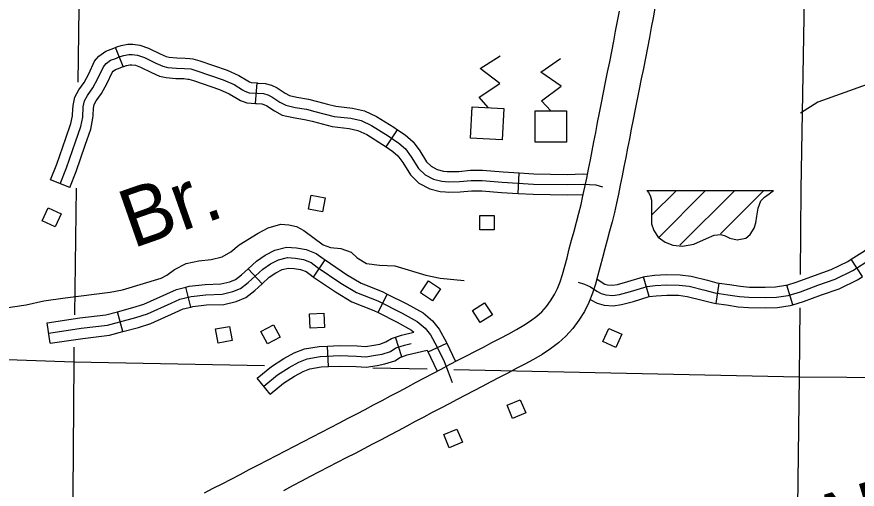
# Model space of a CAD drawing. Extents: x 1370130 to 1380143, y 377636 to 380256.
# Drawn here: x 1377386.4 to 1377557.8, y 379444.4 to 379540.8 of the extents above; entities that cross this region are included whole.
import ezdxf

# ---------------------------------------------------------------- set-up
doc = ezdxf.new("R2010")
doc.units = 0
for name, color, linetype in [('Level 10', 7, 'Continuous'), ('Level 32', 7, 'Continuous'), ('Level 35', 7, 'Continuous'), ('Level 40', 7, 'Continuous'), ('Level 45', 7, 'Continuous'), ('Level 5', 7, 'Continuous'), ('Level 56', 7, 'Continuous'), ('Level 57', 7, 'Continuous')]:
    doc.layers.add(name, color=color, linetype=linetype)

msp = doc.modelspace()

# ---------------------------------------------------------------- linework, layer by layer
at = {"layer": 'Level 10'}
for p, q in [((1377508.88, 379539.89), (1377509.27, 379541.91)), ((1377516.52, 379542.55), (1377516.14, 379540.59)), ((1377508.49, 379537.84), (1377508.88, 379539.89)), ((1377516.14, 379540.59), (1377515.76, 379538.58)), ((1377515.76, 379538.58), (1377515.37, 379536.55)), ((1377508.11, 379535.78), (1377508.49, 379537.84)), ((1377515.37, 379536.55), (1377514.98, 379534.47)), ((1377507.7, 379533.7), (1377508.11, 379535.78)), ((1377514.98, 379534.47), (1377514.57, 379532.36)), ((1377507.29, 379531.61), (1377507.7, 379533.7)), ((1377506.86, 379529.51), (1377507.29, 379531.61)), ((1377514.57, 379532.36), (1377514.15, 379530.23)), ((1377506.44, 379527.41), (1377506.86, 379529.51)), ((1377514.15, 379530.23), (1377513.72, 379528.12)), ((1377513.72, 379528.12), (1377513.3, 379526.03)), ((1377506.02, 379525.31), (1377506.44, 379527.41)), ((1377513.3, 379526.03), (1377512.89, 379523.96)), ((1377505.62, 379523.24), (1377506.02, 379525.31)), ((1377505.22, 379521.22), (1377505.62, 379523.24)), ((1377512.89, 379523.96), (1377512.49, 379521.9)), ((1377504.82, 379519.2), (1377505.22, 379521.22)), ((1377512.49, 379521.9), (1377512.09, 379519.86)), ((1377504.43, 379517.2), (1377504.82, 379519.2)), ((1377512.09, 379519.86), (1377511.69, 379517.85)), ((1377511.69, 379517.85), (1377511.31, 379515.89)), ((1377504.07, 379515.27), (1377504.43, 379517.2)), ((1377511.31, 379515.89), (1377510.95, 379513.97)), ((1377503.72, 379513.41), (1377504.07, 379515.27)), ((1377510.95, 379513.97), (1377510.59, 379512.05)), ((1377503.34, 379511.57), (1377503.72, 379513.41)), ((1377502.96, 379509.7), (1377503.34, 379511.57)), ((1377510.59, 379512.05), (1377510.2, 379510.16)), ((1377502.59, 379507.85), (1377502.96, 379509.7)), ((1377510.2, 379510.16), (1377509.82, 379508.31)), ((1377502.22, 379506.03), (1377502.59, 379507.85)), ((1377509.82, 379508.31), (1377509.45, 379506.46)), ((1377501.84, 379504.24), (1377502.22, 379506.03)), ((1377509.45, 379506.46), (1377509.07, 379504.62)), ((1377501.44, 379502.47), (1377501.84, 379504.24)), ((1377509.07, 379504.62), (1377508.68, 379502.75)), ((1377500.99, 379500.7), (1377501.44, 379502.47)), ((1377508.68, 379502.75), (1377508.25, 379500.84)), ((1377500.51, 379498.89), (1377500.99, 379500.7)), ((1377508.25, 379500.84), (1377507.77, 379498.93)), ((1377500.02, 379497.06), (1377500.51, 379498.89)), ((1377507.77, 379498.93), (1377507.27, 379497.07)), ((1377499.53, 379495.24), (1377500.02, 379497.06)), ((1377507.27, 379497.07), (1377506.77, 379495.24)), ((1377499.04, 379493.42), (1377499.53, 379495.24)), ((1377506.77, 379495.24), (1377506.29, 379493.43)), ((1377498.58, 379491.63), (1377499.04, 379493.42)), ((1377506.29, 379493.43), (1377505.81, 379491.64)), ((1377498.12, 379489.88), (1377498.58, 379491.63)), ((1377505.81, 379491.64), (1377505.35, 379489.86)), ((1377497.68, 379488.24), (1377498.12, 379489.88)), ((1377505.35, 379489.86), (1377504.89, 379488.08)), ((1377497.2, 379486.74), (1377497.68, 379488.24)), ((1377496.66, 379485.37), (1377497.2, 379486.74)), ((1377504.89, 379488.08), (1377504.39, 379486.26)), ((1377496.03, 379484.11), (1377496.66, 379485.37)), ((1377504.39, 379486.26), (1377503.8, 379484.39)), ((1377495.22, 379482.82), (1377496.03, 379484.11)), ((1377503.8, 379484.39), (1377503.06, 379482.52)), ((1377493.44, 379480.63), (1377494.37, 379481.66)), ((1377494.37, 379481.66), (1377495.22, 379482.82)), ((1377503.06, 379482.52), (1377502.15, 379480.69)), ((1377491.14, 379478.76), (1377492.4, 379479.71)), ((1377492.4, 379479.71), (1377493.44, 379480.63)), ((1377502.15, 379480.69), (1377501.02, 379478.88)), ((1377489.78, 379477.85), (1377491.14, 379478.76)), ((1377501.02, 379478.88), (1377499.79, 379477.22)), ((1377486.7, 379476.11), (1377488.3, 379476.98)), ((1377488.3, 379476.98), (1377489.78, 379477.85)), ((1377499.79, 379477.22), (1377498.35, 379475.63)), ((1377483.27, 379474.34), (1377485.01, 379475.23)), ((1377485.01, 379475.23), (1377486.7, 379476.11)), ((1377498.35, 379475.63), (1377496.83, 379474.29)), ((1377479.8, 379472.51), (1377481.53, 379473.42)), ((1377481.53, 379473.42), (1377483.27, 379474.34)), ((1377495.2, 379473.06), (1377493.5, 379471.92)), ((1377496.83, 379474.29), (1377495.2, 379473.06)), ((1377476.35, 379470.73), (1377478.09, 379471.62)), ((1377478.09, 379471.62), (1377479.8, 379472.51)), ((1377493.5, 379471.92), (1377491.75, 379470.89)), ((1377472.92, 379468.93), (1377474.62, 379469.83)), ((1377474.62, 379469.83), (1377476.35, 379470.73)), ((1377489.99, 379469.94), (1377488.24, 379469.02)), ((1377491.75, 379470.89), (1377489.99, 379469.94)), ((1377469.54, 379467.13), (1377471.23, 379468.04)), ((1377471.23, 379468.04), (1377472.92, 379468.93)), ((1377486.5, 379468.12), (1377484.78, 379467.23)), ((1377488.24, 379469.02), (1377486.5, 379468.12)), ((1377466.09, 379465.31), (1377467.83, 379466.23)), ((1377467.83, 379466.23), (1377469.54, 379467.13)), ((1377483.05, 379466.31), (1377481.31, 379465.4)), ((1377484.78, 379467.23), (1377483.05, 379466.31)), ((1377462.6, 379463.45), (1377464.34, 379464.38)), ((1377464.34, 379464.38), (1377466.09, 379465.31)), ((1377479.57, 379464.51), (1377477.87, 379463.62)), ((1377481.31, 379465.4), (1377479.57, 379464.51)), ((1377459.13, 379461.61), (1377460.87, 379462.53)), ((1377460.87, 379462.53), (1377462.6, 379463.45)), ((1377476.19, 379462.74), (1377474.53, 379461.86)), ((1377477.87, 379463.62), (1377476.19, 379462.74)), ((1377457.41, 379460.69), (1377459.13, 379461.61)), ((1377472.83, 379460.96), (1377471.1, 379460.04)), ((1377474.53, 379461.86), (1377472.83, 379460.96)), ((1377453.95, 379458.88), (1377455.7, 379459.78)), ((1377455.7, 379459.78), (1377457.41, 379460.69)), ((1377469.37, 379459.12), (1377467.63, 379458.2)), ((1377471.1, 379460.04), (1377469.37, 379459.12)), ((1377450.35, 379457.01), (1377452.16, 379457.95)), ((1377452.16, 379457.95), (1377453.95, 379458.88)), ((1377467.63, 379458.2), (1377465.89, 379457.27)), ((1377446.66, 379455.11), (1377448.51, 379456.07)), ((1377448.51, 379456.07), (1377450.35, 379457.01)), ((1377464.15, 379456.35), (1377462.43, 379455.44)), ((1377465.89, 379457.27), (1377464.15, 379456.35)), ((1377443, 379453.19), (1377444.82, 379454.14)), ((1377444.82, 379454.14), (1377446.66, 379455.11)), ((1377460.7, 379454.51), (1377458.94, 379453.58)), ((1377462.43, 379455.44), (1377460.7, 379454.51)), ((1377439.35, 379451.28), (1377441.17, 379452.23)), ((1377441.17, 379452.23), (1377443, 379453.19)), ((1377457.17, 379452.66), (1377455.38, 379451.73)), ((1377458.94, 379453.58), (1377457.17, 379452.66)), ((1377437.52, 379450.32), (1377439.35, 379451.28)), ((1377453.56, 379450.79), (1377451.72, 379449.84)), ((1377455.38, 379451.73), (1377453.56, 379450.79)), ((1377433.8, 379448.41), (1377435.67, 379449.37)), ((1377435.67, 379449.37), (1377437.52, 379450.32)), ((1377449.89, 379448.9), (1377448.07, 379447.94)), ((1377451.72, 379449.84), (1377449.89, 379448.9)), ((1377430.07, 379446.47), (1377431.92, 379447.44)), ((1377431.92, 379447.44), (1377433.8, 379448.41)), ((1377448.07, 379447.94), (1377446.24, 379446.99)), ((1377426.46, 379444.61), (1377428.26, 379445.54)), ((1377428.26, 379445.54), (1377430.07, 379446.47)), ((1377444.42, 379446.04), (1377442.59, 379445.08)), ((1377446.24, 379446.99), (1377444.42, 379446.04)), ((1377424.68, 379443.69), (1377426.46, 379444.61)), ((1377442.59, 379445.08), (1377440.75, 379444.11))]:
    msp.add_line(p, q, dxfattribs=at)
at = {"layer": 'Level 32'}
for p, q in [((1377446.92, 379487.7), (1377449.28, 379491.18)), ((1377558.84, 379487.8), (1377556.54, 379491.31)), ((1377436.41, 379486.3), (1377433.58, 379489.4)), ((1377515.36, 379483.71), (1377514.15, 379487.73)), ((1377529.02, 379482.31), (1377529.63, 379486.47)), ((1377421.84, 379481.55), (1377420.86, 379485.63)), ((1377544.61, 379482.05), (1377543.41, 379486.07)), ((1377460.05, 379480.46), (1377461.93, 379484.22)), ((1377408.03, 379476.57), (1377406.94, 379480.63)), ((1377393.22, 379474.19), (1377392.59, 379478.34)), ((1377464.87, 379471.43), (1377463.59, 379475.43)), ((1377449.92, 379469.44), (1377449.72, 379473.63)), ((1377470.25, 379472.42), (1377474.05, 379474.2)), ((1377438.07, 379463.82), (1377435.42, 379467.08))]:
    msp.add_line(p, q, dxfattribs=at)
for points in [[(1377556.54, 379491.31), (1377559.22, 379493.07), (1377563.09, 379496.16), (1377564.93, 379497.54), (1377566.49, 379499.14), (1377567.34, 379500.24)], [(1377433.58, 379489.4), (1377435.25, 379490.92), (1377437.03, 379492.18), (1377439.02, 379493.17), (1377441.37, 379493.76), (1377443.44, 379493.65), (1377445.42, 379493.32), (1377447.41, 379492.5), (1377448.86, 379491.46), (1377449.28, 379491.18)], [(1377392.9, 379476.27), (1377399.54, 379477.27), (1377404.91, 379477.9), (1377410.64, 379479.45), (1377413.01, 379480.18), (1377417.83, 379482.36), (1377419.65, 379483.18), (1377421.92, 379483.73), (1377424.92, 379484.09), (1377428.29, 379484.18), (1377430.47, 379484.73), (1377432.02, 379485.37), (1377433.56, 379486.55), (1377436.57, 379489.28), (1377438.11, 379490.37), (1377439.75, 379491.19), (1377441.57, 379491.65), (1377443.21, 379491.56), (1377444.84, 379491.28), (1377446.39, 379490.65), (1377447.66, 379489.74), (1377452.48, 379486.46), (1377455.67, 379484.55), (1377460.03, 379482.82), (1377464.95, 379480.36), (1377468.04, 379478.63), (1377469.68, 379477.27), (1377470.77, 379475.9), (1377472.04, 379473.53), (1377473.5, 379470.44), (1377474.38, 379468.35), (1377475.18, 379466.17)], [(1377449.28, 379491.18), (1377453.62, 379488.23), (1377456.6, 379486.44), (1377460.89, 379484.74), (1377461.93, 379484.22)], [(1377500.84, 379486.63), (1377502.16, 379486.25), (1377503.4, 379485.67), (1377504.63, 379484.79), (1377505.52, 379484.31), (1377506.49, 379484.04), (1377507.94, 379483.95), (1377509.31, 379484.13), (1377511.56, 379484.75), (1377514.91, 379485.76), (1377516.58, 379485.98), (1377518.92, 379486.11), (1377521.48, 379486.07), (1377523.5, 379485.81), (1377526.68, 379485.01), (1377528.71, 379484.48), (1377531.4, 379484.09), (1377533.73, 379483.73), (1377535.67, 379483.56), (1377539.02, 379483.51), (1377541.32, 379483.6), (1377543.65, 379483.95), (1377546.17, 379484.7), (1377549.74, 379486.03), (1377553.27, 379487.26), (1377556.88, 379489.03), (1377560.45, 379491.36)], [(1377543.41, 379486.07), (1377545.5, 379486.7), (1377549.03, 379488), (1377552.46, 379489.2), (1377555.84, 379490.86), (1377556.54, 379491.31)], [(1377420.86, 379485.63), (1377421.55, 379485.8), (1377424.77, 379486.19), (1377428, 379486.28), (1377429.81, 379486.73), (1377430.96, 379487.2), (1377432.22, 379488.16), (1377433.58, 379489.4)], [(1377436.41, 379486.3), (1377437.88, 379487.64), (1377439.19, 379488.57), (1377440.48, 379489.21), (1377441.77, 379489.53), (1377442.97, 379489.47), (1377444.26, 379489.25), (1377445.37, 379488.8), (1377446.46, 379488.01), (1377446.92, 379487.7)], [(1377514.15, 379487.73), (1377514.46, 379487.82), (1377516.39, 379488.07), (1377518.88, 379488.22), (1377521.63, 379488.17), (1377523.9, 379487.87), (1377527.2, 379487.05), (1377529.13, 379486.54), (1377529.63, 379486.47)], [(1377446.92, 379487.7), (1377451.35, 379484.69), (1377454.73, 379482.66), (1377459.18, 379480.9), (1377460.05, 379480.46)], [(1377504.69, 379487.33), (1377505.75, 379486.57), (1377506.31, 379486.27), (1377506.83, 379486.12), (1377507.87, 379486.06), (1377508.89, 379486.19), (1377510.97, 379486.77), (1377514.15, 379487.73)], [(1377529.63, 379486.47), (1377531.71, 379486.16), (1377533.99, 379485.82), (1377535.78, 379485.65), (1377539, 379485.61), (1377541.12, 379485.69), (1377543.19, 379486.01), (1377543.41, 379486.07)], [(1377544.61, 379482.05), (1377546.83, 379482.71), (1377550.45, 379484.05), (1377554.08, 379485.32), (1377557.92, 379487.2), (1377558.84, 379487.8)], [(1377406.94, 379480.63), (1377410.06, 379481.47), (1377412.26, 379482.15), (1377416.96, 379484.28), (1377418.96, 379485.18), (1377420.86, 379485.63)], [(1377421.84, 379481.55), (1377422.29, 379481.66), (1377425.08, 379482), (1377428.57, 379482.09), (1377431.13, 379482.73), (1377433.07, 379483.53), (1377434.91, 379484.94), (1377436.41, 379486.3)], [(1377461.93, 379484.22), (1377465.93, 379482.22), (1377469.23, 379480.37), (1377471.18, 379478.74), (1377472.53, 379477.06), (1377473.92, 379474.48), (1377474.05, 379474.2)], [(1377503.3, 379483.13), (1377504.72, 379482.35), (1377506.14, 379481.96), (1377508.01, 379481.85), (1377509.72, 379482.07), (1377512.14, 379482.73), (1377515.36, 379483.71)], [(1377515.35, 379483.7), (1377516.78, 379483.89), (1377518.96, 379484.01), (1377521.32, 379483.97), (1377523.11, 379483.74), (1377526.16, 379482.98), (1377528.29, 379482.42), (1377529.02, 379482.31)], [(1377408.03, 379476.57), (1377411.22, 379477.43), (1377413.75, 379478.21), (1377418.69, 379480.45), (1377420.33, 379481.19), (1377421.84, 379481.55)], [(1377529.02, 379482.31), (1377531.09, 379482.01), (1377533.48, 379481.65), (1377535.56, 379481.46), (1377539.05, 379481.41), (1377541.52, 379481.51), (1377544.11, 379481.9), (1377544.61, 379482.05)], [(1377392.59, 379478.34), (1377399.26, 379479.35), (1377404.51, 379479.97), (1377406.94, 379480.63)], [(1377460.05, 379480.46), (1377463.96, 379478.5), (1377466.84, 379476.89), (1377467.36, 379476.46)], [(1377393.22, 379474.19), (1377399.82, 379475.19), (1377405.31, 379475.84), (1377408.03, 379476.57)], [(1377463.59, 379475.43), (1377464.86, 379475.84), (1377467.36, 379476.46)], [(1377449.72, 379473.63), (1377452.21, 379473.76), (1377455.77, 379473.66), (1377457.46, 379473.56), (1377459.19, 379473.81), (1377460.39, 379474.03), (1377461.66, 379474.45), (1377462.78, 379475.17), (1377463.59, 379475.43)], [(1377435.42, 379467.08), (1377438.32, 379469.45), (1377440.87, 379471.05), (1377442.97, 379472.26), (1377445.05, 379473.04), (1377448.02, 379473.55), (1377449.72, 379473.63)], [(1377436.74, 379465.45), (1377439.55, 379467.74), (1377441.95, 379469.25), (1377443.87, 379470.36), (1377445.6, 379471.01), (1377448.25, 379471.46), (1377452.24, 379471.66), (1377455.68, 379471.56), (1377457.55, 379471.45), (1377459.53, 379471.73), (1377460.92, 379471.99), (1377462.58, 379472.54), (1377463.69, 379473.26), (1377465.44, 379473.82), (1377466.82, 379474.16)], [(1377464.87, 379471.43), (1377466.01, 379471.8), (1377470.06, 379472.81)], [(1377470.06, 379472.81), (1377472.09, 379468.49)], [(1377474.05, 379474.2), (1377475.81, 379470.45)], [(1377449.92, 379469.44), (1377452.26, 379469.55), (1377455.59, 379469.46), (1377457.64, 379469.34), (1377459.88, 379469.66), (1377461.44, 379469.96), (1377463.49, 379470.63), (1377464.6, 379471.34), (1377464.87, 379471.43)], [(1377438.07, 379463.82), (1377440.78, 379466.03), (1377443.04, 379467.46), (1377444.77, 379468.45), (1377446.15, 379468.97), (1377448.48, 379469.37), (1377449.92, 379469.44)]]:
    msp.add_lwpolyline(points, dxfattribs=at)
at = {"layer": 'Level 35'}
for points in [[(1377562.15, 379528.24), (1377559.82, 379526.98), (1377549.72, 379523.39), (1377546.22, 379521.11)], [(1377384.17, 379481.42), (1377388.31, 379482.04), (1377391.92, 379482.82), (1377396.26, 379483.48), (1377405.44, 379484.59), (1377407.97, 379485.1), (1377415.85, 379487.49), (1377416.97, 379488.11), (1377418.53, 379489.24), (1377420.92, 379490.47), (1377423.5, 379490.98), (1377426.03, 379491.3), (1377428.25, 379491.83), (1377430.03, 379492.82), (1377431.74, 379494.28), (1377435.57, 379496.63), (1377437.62, 379497.74), (1377440.2, 379498.45), (1377441.88, 379498.37), (1377443.43, 379498.01), (1377444.94, 379497.16), (1377448.87, 379494.25), (1377450.37, 379493.74), (1377452.48, 379493.54), (1377454.58, 379492.74), (1377455.76, 379491.64), (1377457.7, 379490.47), (1377460.34, 379490.15), (1377463.45, 379490.01), (1377469.81, 379488.08), (1377472.74, 379487.48), (1377477.62, 379487.01)]]:
    msp.add_lwpolyline(points, dxfattribs=at)
at = {"layer": 'Level 45'}
for p, q in [((1377408.05, 379530.62), (1377406.52, 379534.53)), ((1377435.09, 379523.09), (1377435.4, 379527.28)), ((1377461.69, 379514.22), (1377464.02, 379517.71)), ((1377488.59, 379504.74), (1377488.84, 379508.94)), ((1377397.18, 379505.95), (1377393.27, 379507.5))]:
    msp.add_line(p, q, dxfattribs=at)
for points in [[(1377397.74, 379520.85), (1377397.85, 379522.68), (1377398.19, 379524.37), (1377399.02, 379525.87), (1377400.12, 379527.4), (1377401.06, 379529.12), (1377402.25, 379531.69), (1377403.14, 379532.77), (1377404.52, 379533.79), (1377405.64, 379534.19), (1377406.52, 379534.53)], [(1377406.52, 379534.53), (1377406.76, 379534.62), (1377407.69, 379534.93), (1377409.06, 379535.18), (1377410.04, 379535.18), (1377411.49, 379535.01), (1377413.25, 379534.4), (1377415.65, 379533.2), (1377416.85, 379532.68), (1377417.48, 379532.52), (1377419.04, 379532.42), (1377420.72, 379532.35), (1377421.67, 379532.26)], [(1377395.22, 379506.73), (1377396.51, 379509.97), (1377398.35, 379515.3), (1377399.45, 379518.43), (1377399.82, 379520.33), (1377399.94, 379522.41), (1377400.18, 379523.64), (1377400.8, 379524.74), (1377401.9, 379526.27), (1377402.94, 379528.17), (1377404.04, 379530.56), (1377404.59, 379531.24), (1377405.51, 379531.91), (1377406.37, 379532.22), (1377407.47, 379532.65), (1377408.21, 379532.89), (1377409.25, 379533.08), (1377409.92, 379533.08), (1377411.03, 379532.95), (1377412.43, 379532.46), (1377414.76, 379531.3), (1377416.17, 379530.69), (1377417.15, 379530.44), (1377418.93, 379530.32), (1377420.58, 379530.26), (1377421.87, 379530.13), (1377423.09, 379529.77), (1377428.48, 379527.93), (1377430.69, 379526.95), (1377432.4, 379525.91), (1377432.89, 379525.6), (1377433.75, 379525.29), (1377435.4, 379525.17), (1377436.69, 379525.11), (1377437.55, 379524.86), (1377438.4, 379524.44), (1377439.99, 379523.39), (1377441.22, 379522.72), (1377443.12, 379522.29), (1377445.45, 379521.92), (1377447.16, 379521.49), (1377451.08, 379520.45), (1377454.51, 379520.08), (1377456.59, 379519.59), (1377458.74, 379518.61), (1377462.11, 379516.47), (1377464.31, 379515), (1377465.66, 379513.83), (1377466.82, 379512.24), (1377468.29, 379509.85), (1377469.64, 379508.56), (1377471.35, 379507.64), (1377473.07, 379507.22), (1377474.42, 379507.09), (1377476.68, 379507.15), (1377479.01, 379507.4), (1377481.28, 379507.4), (1377485.38, 379507.03), (1377491.75, 379506.66), (1377498.61, 379506.54), (1377501.85, 379506.66), (1377504.43, 379506.48), (1377505.8, 379506.11)], [(1377421.67, 379532.26), (1377422.27, 379532.21), (1377423.73, 379531.77), (1377429.25, 379529.89), (1377431.66, 379528.81), (1377433.5, 379527.69), (1377433.81, 379527.5), (1377434.19, 379527.37), (1377435.4, 379527.28)], [(1377401.94, 379520.61), (1377402.03, 379522.14), (1377402.18, 379522.91), (1377402.57, 379523.62), (1377403.68, 379525.15), (1377404.82, 379527.23), (1377405.84, 379529.44), (1377406.05, 379529.7), (1377406.51, 379530.04), (1377407.1, 379530.25), (1377408.05, 379530.62)], [(1377408.05, 379530.62), (1377408.19, 379530.67), (1377408.73, 379530.85), (1377409.43, 379530.98), (1377409.81, 379530.98), (1377410.56, 379530.89), (1377411.62, 379530.52), (1377413.87, 379529.4), (1377415.49, 379528.69), (1377416.82, 379528.36), (1377418.81, 379528.22), (1377420.44, 379528.16), (1377421.27, 379528.08)], [(1377421.27, 379528.08), (1377421.46, 379528.06), (1377422.45, 379527.77), (1377427.71, 379525.97), (1377429.71, 379525.08), (1377431.3, 379524.12), (1377431.97, 379523.7), (1377433.31, 379523.22), (1377435.09, 379523.09)], [(1377435.4, 379527.28), (1377435.53, 379527.27), (1377437.03, 379527.2), (1377438.31, 379526.83), (1377439.45, 379526.26), (1377441.08, 379525.2), (1377441.97, 379524.7), (1377443.51, 379524.35), (1377445.87, 379523.98), (1377447.69, 379523.53), (1377449.75, 379522.98)], [(1377435.09, 379523.09), (1377435.27, 379523.07), (1377436.34, 379523.02), (1377436.78, 379522.9), (1377437.35, 379522.61), (1377438.91, 379521.59), (1377440.47, 379520.74), (1377442.72, 379520.23), (1377445.03, 379519.86), (1377446.64, 379519.46), (1377448.67, 379518.92)], [(1377449.75, 379522.98), (1377451.46, 379522.52), (1377454.86, 379522.16), (1377457.28, 379521.59), (1377459.74, 379520.46), (1377463.25, 379518.23), (1377464.02, 379517.71)], [(1377393.27, 379507.5), (1377394.54, 379510.7), (1377396.36, 379516), (1377397.42, 379518.98), (1377397.73, 379520.59), (1377397.74, 379520.85)], [(1377397.18, 379505.95), (1377398.48, 379509.24), (1377400.33, 379514.61), (1377401.48, 379517.88), (1377401.9, 379520.07), (1377401.94, 379520.61)], [(1377448.67, 379518.92), (1377450.7, 379518.38), (1377454.16, 379518.01), (1377455.91, 379517.6), (1377457.73, 379516.76), (1377460.96, 379514.71), (1377461.69, 379514.22)], [(1377464.02, 379517.71), (1377465.58, 379516.67), (1377467.21, 379515.27), (1377468.57, 379513.41), (1377469.94, 379511.18), (1377470.88, 379510.28), (1377472.12, 379509.62), (1377473.42, 379509.29), (1377474.16, 379509.23)], [(1377461.69, 379514.22), (1377463.04, 379513.32), (1377464.1, 379512.4), (1377465.08, 379511.07), (1377466.64, 379508.52), (1377468.39, 379506.85), (1377470.59, 379505.67), (1377472.72, 379505.14), (1377473.78, 379505.04)], [(1377474.16, 379509.23), (1377474.48, 379509.2), (1377476.54, 379509.25), (1377478.9, 379509.5), (1377481.37, 379509.5), (1377485.53, 379509.13), (1377488.84, 379508.94)], [(1377488.84, 379508.94), (1377491.83, 379508.76), (1377498.59, 379508.64), (1377501.89, 379508.77), (1377502.76, 379508.7)], [(1377473.78, 379505.04), (1377474.35, 379504.99), (1377476.82, 379505.06), (1377479.12, 379505.3), (1377481.18, 379505.3), (1377485.23, 379504.94), (1377488.59, 379504.74)], [(1377488.59, 379504.74), (1377491.67, 379504.57), (1377498.63, 379504.44), (1377501.91, 379504.56)]]:
    msp.add_lwpolyline(points, dxfattribs=at)
at = {"layer": 'Level 5'}
for points in [[(1377399.44, 379572.58), (1377398.8, 379527.45)], [(1377547.18, 379560.13), (1377546.28, 379505.65), (1377546.1, 379488.22)], [(1377398.49, 379505.79), (1377398.13, 379479.99)], [(1377546.03, 379481.4), (1377545.89, 379467.36)], [(1377265.16, 379475.11), (1377397.99, 379470.43)], [(1377398.04, 379473.41), (1377397.99, 379470.43)], [(1377397.99, 379470.43), (1377397.69, 379425.59)], [(1377397.99, 379470.43), (1377436.92, 379469.62)], [(1377458.99, 379469.17), (1377470.06, 379468.94)], [(1377475.5, 379468.82), (1377545.89, 379467.36)], [(1377545.89, 379467.36), (1377544.7, 379372.02)], [(1377545.89, 379467.36), (1377643.17, 379466.67)]]:
    msp.add_lwpolyline(points, dxfattribs=at)
at = {"layer": 'Level 56'}
for points in [[(1377448.72, 379500.98), (1377445.86, 379501.54), (1377446.42, 379504.41), (1377449.28, 379503.85)], [(1377392.81, 379501.78), (1377395.46, 379500.57), (1377394.24, 379497.91), (1377391.59, 379499.13)], [(1377480.81, 379497.34), (1377480.81, 379500.26), (1377483.73, 379500.26), (1377483.73, 379497.34)], [(1377472.78, 379485.27), (1377471.15, 379482.85), (1377468.72, 379484.49), (1377470.35, 379486.9)], [(1377483.36, 379479.96), (1377480.9, 379478.39), (1377479.33, 379480.86), (1377481.79, 379482.42)], [(1377448.99, 379480.34), (1377449.16, 379477.43), (1377446.24, 379477.27), (1377446.07, 379480.18)], [(1377438.76, 379477.98), (1377440.12, 379475.4), (1377437.53, 379474.04), (1377436.18, 379476.62)], [(1377429.78, 379477.62), (1377430.29, 379474.76), (1377427.42, 379474.24), (1377426.9, 379477.11)], [(1377507.11, 379477.21), (1377509.77, 379476.01), (1377508.57, 379473.34), (1377505.91, 379474.54)], [(1377487.49, 379458.84), (1377486.36, 379461.53), (1377489.06, 379462.66), (1377490.18, 379459.97)], [(1377473.44, 379455.55), (1377476.12, 379456.68), (1377477.26, 379453.99), (1377474.58, 379452.85)]]:
    msp.add_lwpolyline(points, close=True, dxfattribs=at)
at = {"layer": 'Level 57'}
for p, q in [((1377514.84, 379505.33), (1377540.71, 379505.33)), ((1377515.9, 379500.36), (1377520.77, 379505.23)), ((1377517.35, 379495.86), (1377526.68, 379505.2)), ((1377521.61, 379494.19), (1377532.67, 379505.24)), ((1377529.9, 379496.53), (1377538.56, 379505.19))]:
    msp.add_line(p, q, dxfattribs=at)
for points in [[(1377482.48, 379522.27), (1377480.68, 379524.37), (1377484.85, 379527.17), (1377480.87, 379530.22), (1377484.98, 379532.79)], [(1377495.29, 379521.62), (1377493.38, 379523.62), (1377497.4, 379526.64), (1377493.26, 379529.47), (1377497.22, 379532.25)], [(1377514.84, 379505.33), (1377515.21, 379504.92), (1377515.55, 379504.31), (1377515.79, 379503.38), (1377515.79, 379501.99), (1377515.82, 379500.17), (1377515.82, 379498.55), (1377516.29, 379497.19), (1377517.18, 379495.8), (1377518.57, 379494.8), (1377520.19, 379494.18), (1377522.16, 379493.98), (1377524.41, 379494.41), (1377527, 379495.57), (1377528.58, 379496.26), (1377529.93, 379496.38), (1377530.86, 379496.11), (1377531.79, 379495.65), (1377533.3, 379495.3), (1377535.04, 379495.61), (1377535.96, 379496.38), (1377536.74, 379497.66), (1377537.08, 379498.78), (1377537.28, 379500.09), (1377537.59, 379501.75), (1377538.13, 379503.26), (1377538.86, 379503.96), (1377539.79, 379504.69), (1377540.71, 379505.33)]]:
    msp.add_lwpolyline(points, dxfattribs=at)
for points in [[(1377478.93, 379516.03), (1377479.27, 379522.44), (1377485.69, 379522.1), (1377485.35, 379515.68)], [(1377492.08, 379515.2), (1377492.08, 379521.62), (1377498.5, 379521.62), (1377498.5, 379515.2)]]:
    msp.add_lwpolyline(points, close=True, dxfattribs=at)

# ---------------------------------------------------------------- texts
at = {"layer": 'Level 35'}
msp.add_text('Br.', height=11.827, rotation=19.2751, dxfattribs=at).set_placement((1377410, 379493.49))
at = {"layer": 'Level 40'}
msp.add_text('ARKANSAS', height=11.827, rotation=16.8546, dxfattribs=at).set_placement((1377550.21, 379430.72))

doc.saveas('drawing.dxf')
